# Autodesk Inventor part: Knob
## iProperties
Shininess: 41.0
Length Units: 11272
Angle Units: 11279
Time Units: 11290
Mass Units: 11286
Length Display Precision: 4
Angle Display Precision: 2
Compacted: True
Manager: Lebovitz
Company: Autodesk
Created: 2000-11
Part Number: Knob
Document SubType Name: Modeling
Designer: The PD Team
Project: Inventor Samples
Density: 0.0
Volumn: 0.0
Area: 0.0
PropertySet Name: Model Information
Control State: 0
Master: False
Checked Out: False
Author: The PD Team
Revision Number: A
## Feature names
1. Revolution1
2. Revolution2
3. Fillet1
